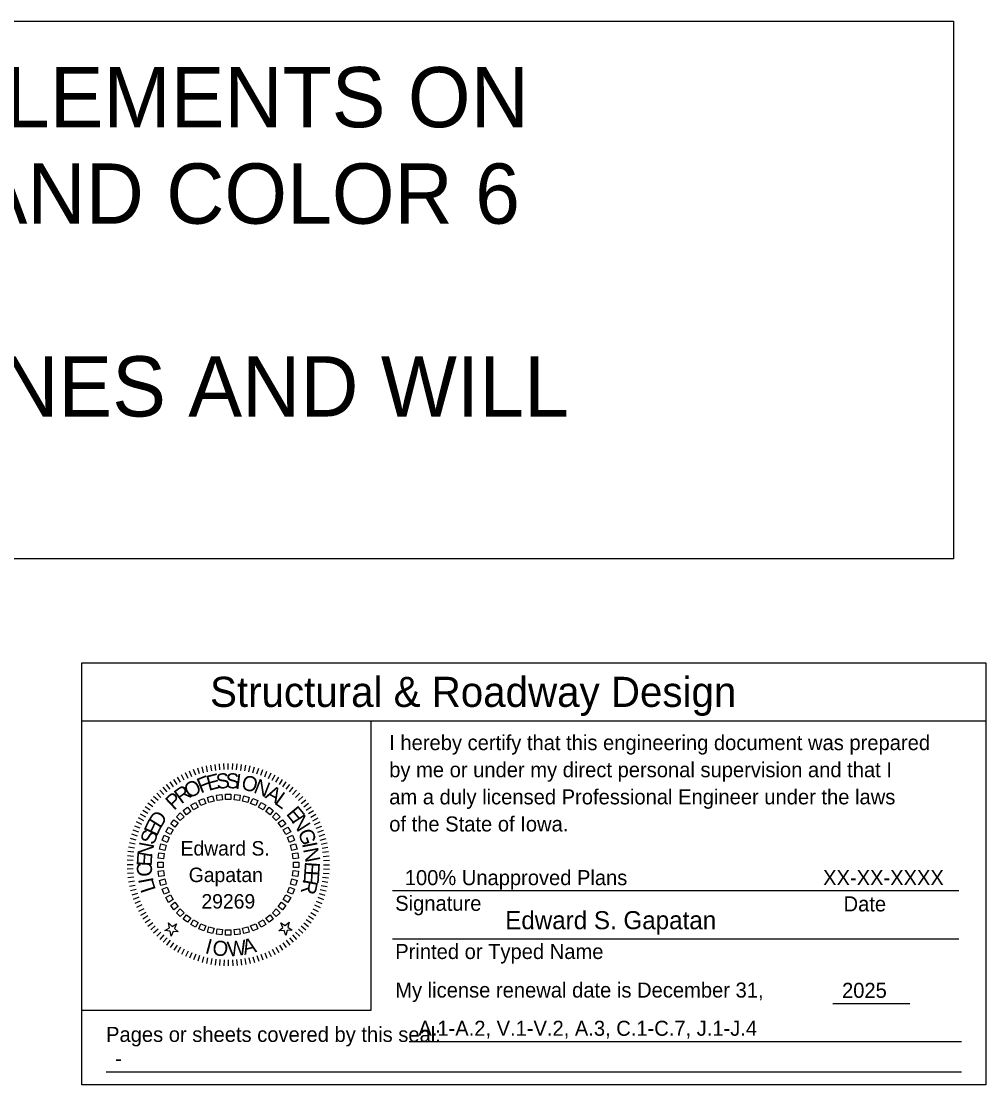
# Model space of a CAD drawing. Extents: x -0.84 to 4.97, y -1.01 to 2.42.
# Drawn here: x 3.618 to 4.285, y -0.653 to 0.082 of the extents above; entities that cross this region are included whole.
import ezdxf

# ---------------------------------------------------------------- set-up
doc = ezdxf.new("R2010")
doc.units = 0
for name, color, linetype in [('Level 1', 7, 'Continuous'), ('Level 2', 7, 'Continuous'), ('SheetGridMajor', 7, 'Continuous'), ('SheetGridMinor', 7, 'Continuous'), ('SheetText', 7, 'Continuous'), ('TextNonPlot', 7, 'Continuous')]:
    doc.layers.add(name, color=color, linetype=linetype)

msp = doc.modelspace()

# ---------------------------------------------------------------- linework, layer by layer
at = {"layer": 'Level 1'}
for p, q in [((3.74438, -0.43744), (3.7433, -0.43342)), ((3.74717, -0.43676), (3.74626, -0.43269)), ((3.74998, -0.4362), (3.74926, -0.4321)), ((3.75282, -0.43576), (3.75228, -0.43163)), ((3.75568, -0.43545), (3.75532, -0.4313)), ((3.75855, -0.43526), (3.75836, -0.4311)), ((3.76142, -0.4352), (3.76142, -0.43103)), ((3.76429, -0.43526), (3.76447, -0.4311)), ((3.76715, -0.43545), (3.76752, -0.4313)), ((3.77001, -0.43576), (3.77055, -0.43163)), ((3.77285, -0.4362), (3.77357, -0.4321)), ((3.77567, -0.43676), (3.77657, -0.43269)), ((3.77846, -0.43744), (3.77953, -0.43342)), ((3.7285, -0.44402), (3.72642, -0.44041)), ((3.73102, -0.44264), (3.72909, -0.43894)), ((3.73359, -0.44137), (3.73183, -0.43759)), ((3.73622, -0.44021), (3.73463, -0.43636)), ((3.7389, -0.43917), (3.73747, -0.43526)), ((3.74162, -0.43825), (3.74037, -0.43427)), ((3.78121, -0.43825), (3.78247, -0.43427)), ((3.78393, -0.43917), (3.78536, -0.43526)), ((3.78661, -0.44021), (3.7882, -0.43636)), ((3.78924, -0.44137), (3.791, -0.43759)), ((3.79181, -0.44264), (3.79374, -0.43894)), ((3.79433, -0.44402), (3.79642, -0.44041)), ((3.7191, -0.4506), (3.71642, -0.44741)), ((3.72134, -0.4488), (3.7188, -0.4455)), ((3.72365, -0.44711), (3.72127, -0.44369)), ((3.72604, -0.44551), (3.7238, -0.442)), ((3.79679, -0.44551), (3.79903, -0.442)), ((3.79918, -0.44711), (3.80157, -0.44369)), ((3.80149, -0.44881), (3.80403, -0.4455)), ((3.80373, -0.4506), (3.80641, -0.44741)), ((3.71288, -0.45656), (3.70981, -0.45374)), ((3.71486, -0.45448), (3.71192, -0.45154)), ((3.71694, -0.4525), (3.71412, -0.44942)), ((3.80589, -0.4525), (3.80871, -0.44943)), ((3.80797, -0.45448), (3.81091, -0.45154)), ((3.80995, -0.45656), (3.81303, -0.45374)), ((3.70749, -0.46327), (3.70407, -0.46088)), ((3.70919, -0.46096), (3.70588, -0.45842)), ((3.71098, -0.45872), (3.70779, -0.45604)), ((3.81185, -0.45872), (3.81504, -0.45604)), ((3.81365, -0.46096), (3.81695, -0.45842)), ((3.81534, -0.46327), (3.81876, -0.46088)), ((3.70302, -0.47064), (3.69932, -0.46871)), ((3.7044, -0.46812), (3.70079, -0.46603)), ((3.70589, -0.46566), (3.70238, -0.46342)), ((3.81694, -0.46566), (3.82045, -0.46342)), ((3.81843, -0.46812), (3.82204, -0.46603)), ((3.81981, -0.47064), (3.82351, -0.46871)), ((3.69955, -0.47852), (3.69564, -0.47709)), ((3.70059, -0.47584), (3.69674, -0.47425)), ((3.70175, -0.47321), (3.69797, -0.47145)), ((3.82108, -0.47321), (3.82486, -0.47145)), ((3.82224, -0.47584), (3.82609, -0.47425)), ((3.82328, -0.47852), (3.82719, -0.47709)), ((3.69783, -0.48399), (3.6938, -0.48292)), ((3.69863, -0.48124), (3.69466, -0.47998)), ((3.8242, -0.48124), (3.82818, -0.47999)), ((3.82501, -0.484), (3.82903, -0.48292)), ((3.69615, -0.49244), (3.69201, -0.4919)), ((3.69658, -0.4896), (3.69248, -0.48888)), ((3.69714, -0.48678), (3.69307, -0.48588)), ((3.82569, -0.48679), (3.82976, -0.48588)), ((3.82625, -0.4896), (3.83035, -0.48888)), ((3.82669, -0.49244), (3.83082, -0.4919)), ((3.69564, -0.49816), (3.69148, -0.49798)), ((3.69583, -0.4953), (3.69168, -0.49493)), ((3.827, -0.4953), (3.83115, -0.49493)), ((3.82719, -0.49816), (3.83135, -0.49798)), ((3.69558, -0.50103), (3.69141, -0.50103)), ((3.69564, -0.5039), (3.69148, -0.50409)), ((3.69583, -0.50677), (3.69168, -0.50713)), ((3.827, -0.50677), (3.83115, -0.50714)), ((3.82719, -0.50391), (3.83135, -0.50409)), ((3.82725, -0.50103), (3.83142, -0.50103)), ((3.69614, -0.50963), (3.69201, -0.51017)), ((3.69658, -0.51247), (3.69248, -0.51319)), ((3.82625, -0.51247), (3.83035, -0.51319)), ((3.82669, -0.50963), (3.83082, -0.51017)), ((3.69714, -0.51528), (3.69307, -0.51618)), ((3.69783, -0.51807), (3.6938, -0.51915)), ((3.69863, -0.52083), (3.69465, -0.52208)), ((3.8242, -0.52083), (3.82818, -0.52208)), ((3.82501, -0.51807), (3.82903, -0.51915)), ((3.82569, -0.51528), (3.82976, -0.51618)), ((3.69955, -0.52355), (3.69564, -0.52497)), ((3.70059, -0.52623), (3.69674, -0.52782)), ((3.70175, -0.52886), (3.69797, -0.53062)), ((3.82108, -0.52886), (3.82486, -0.53062)), ((3.82224, -0.52623), (3.82609, -0.52782)), ((3.82328, -0.52355), (3.82719, -0.52498)), ((3.70302, -0.53143), (3.69932, -0.53336)), ((3.7044, -0.53395), (3.70079, -0.53603)), ((3.70589, -0.53641), (3.70238, -0.53864)), ((3.81694, -0.53641), (3.82045, -0.53864)), ((3.81843, -0.53395), (3.82204, -0.53603)), ((3.81981, -0.53143), (3.82351, -0.53336)), ((3.70749, -0.53879), (3.70407, -0.54118)), ((3.70919, -0.54111), (3.70588, -0.54365)), ((3.71098, -0.54335), (3.70779, -0.54603)), ((3.81185, -0.54335), (3.81504, -0.54603)), ((3.81364, -0.54111), (3.81695, -0.54365)), ((3.81534, -0.53879), (3.81876, -0.54118)), ((3.71288, -0.54551), (3.7098, -0.54832)), ((3.71486, -0.54758), (3.71192, -0.55053)), ((3.71694, -0.54957), (3.71412, -0.55264)), ((3.7191, -0.55146), (3.71642, -0.55466)), ((3.80373, -0.55147), (3.80641, -0.55466)), ((3.80589, -0.54957), (3.80871, -0.55264)), ((3.80797, -0.54759), (3.81091, -0.55053)), ((3.80995, -0.54551), (3.81302, -0.54833)), ((3.72134, -0.55326), (3.7188, -0.55657)), ((3.72365, -0.55496), (3.72126, -0.55837)), ((3.72604, -0.55656), (3.7238, -0.56007)), ((3.7285, -0.55805), (3.72641, -0.56165)), ((3.79433, -0.55805), (3.79642, -0.56166)), ((3.79679, -0.55656), (3.79903, -0.56007)), ((3.79918, -0.55496), (3.80157, -0.55837)), ((3.80149, -0.55326), (3.80403, -0.55657)), ((3.73102, -0.55943), (3.72909, -0.56312)), ((3.73359, -0.5607), (3.73183, -0.56447)), ((3.73622, -0.56186), (3.73463, -0.5657)), ((3.7389, -0.5629), (3.73747, -0.56681)), ((3.74162, -0.56382), (3.74036, -0.56779)), ((3.74438, -0.56462), (3.7433, -0.56865)), ((3.74717, -0.56531), (3.74626, -0.56937)), ((3.74998, -0.56587), (3.74926, -0.56997)), ((3.77285, -0.56587), (3.77357, -0.56997)), ((3.77566, -0.56531), (3.77657, -0.56937)), ((3.77845, -0.56462), (3.77953, -0.56865)), ((3.78121, -0.56382), (3.78246, -0.56779)), ((3.78393, -0.5629), (3.78536, -0.56681)), ((3.78661, -0.56186), (3.7882, -0.56571)), ((3.78924, -0.5607), (3.791, -0.56448)), ((3.79181, -0.55943), (3.79374, -0.56312)), ((3.75282, -0.5663), (3.75228, -0.57043)), ((3.75568, -0.56662), (3.75531, -0.57077)), ((3.75854, -0.5668), (3.75836, -0.57097)), ((3.76142, -0.56687), (3.76142, -0.57103)), ((3.76429, -0.5668), (3.76447, -0.57097)), ((3.76715, -0.56662), (3.76752, -0.57077)), ((3.77001, -0.5663), (3.77055, -0.57043))]:
    msp.add_line(p, q, dxfattribs=at)
for points in [[(3.74593, -0.45874), (3.74246, -0.46018), (3.74103, -0.45671), (3.74449, -0.45528)], [(3.75158, -0.45708), (3.74796, -0.45805), (3.74699, -0.45443), (3.75061, -0.45346)], [(3.7574, -0.45617), (3.75368, -0.45666), (3.75319, -0.45295), (3.75691, -0.45246)], [(3.76329, -0.45603), (3.75954, -0.45603), (3.75954, -0.45228), (3.76329, -0.45228)], [(3.76915, -0.45666), (3.76543, -0.45617), (3.76592, -0.45246), (3.76964, -0.45295)], [(3.77487, -0.45805), (3.77125, -0.45708), (3.77222, -0.45346), (3.77584, -0.45443)], [(3.78037, -0.46018), (3.7769, -0.45874), (3.77834, -0.45528), (3.7818, -0.45671)], [(3.73551, -0.46419), (3.73253, -0.46647), (3.73025, -0.4635), (3.73322, -0.46122)], [(3.74054, -0.46112), (3.73729, -0.463), (3.73542, -0.45975), (3.73866, -0.45788)], [(3.78554, -0.463), (3.78229, -0.46113), (3.78417, -0.45788), (3.78741, -0.45975)], [(3.7903, -0.46647), (3.78732, -0.46419), (3.78961, -0.46122), (3.79258, -0.4635)], [(3.72685, -0.47215), (3.72457, -0.47513), (3.7216, -0.47284), (3.72388, -0.46987)], [(3.73092, -0.46789), (3.72827, -0.47054), (3.72562, -0.46789), (3.72827, -0.46524)], [(3.79456, -0.47054), (3.79191, -0.46789), (3.79456, -0.46524), (3.79721, -0.46789)], [(3.79826, -0.47513), (3.79598, -0.47215), (3.79895, -0.46987), (3.80123, -0.47284)], [(3.72338, -0.47691), (3.72151, -0.48016), (3.71826, -0.47828), (3.72013, -0.47504)], [(3.80133, -0.48016), (3.79945, -0.47691), (3.8027, -0.47503), (3.80457, -0.47828)], [(3.72056, -0.48208), (3.71912, -0.48555), (3.71566, -0.48411), (3.71709, -0.48065)], [(3.80371, -0.48555), (3.80227, -0.48208), (3.80574, -0.48065), (3.80717, -0.48411)], [(3.71843, -0.48758), (3.71746, -0.4912), (3.71384, -0.49023), (3.71481, -0.48661)], [(3.80537, -0.4912), (3.8044, -0.48758), (3.80802, -0.4866), (3.80899, -0.49023)], [(3.71641, -0.49916), (3.71641, -0.50291), (3.71266, -0.50291), (3.71266, -0.49916)], [(3.71704, -0.4933), (3.71656, -0.49702), (3.71284, -0.49653), (3.71333, -0.49281)], [(3.80628, -0.49702), (3.80579, -0.4933), (3.8095, -0.49281), (3.80999, -0.49653)], [(3.80642, -0.50291), (3.80642, -0.49916), (3.81017, -0.49916), (3.81017, -0.50291)], [(3.71655, -0.50505), (3.71704, -0.50877), (3.71333, -0.50926), (3.71284, -0.50554)], [(3.80579, -0.50877), (3.80628, -0.50505), (3.80999, -0.50554), (3.8095, -0.50926)], [(3.71746, -0.51087), (3.71843, -0.51449), (3.71481, -0.51546), (3.71384, -0.51184)], [(3.8044, -0.51449), (3.80537, -0.51087), (3.80899, -0.51184), (3.80802, -0.51546)], [(3.71912, -0.51652), (3.72056, -0.51999), (3.71709, -0.52142), (3.71566, -0.51796)], [(3.72151, -0.52191), (3.72338, -0.52516), (3.72013, -0.52703), (3.71826, -0.52379)], [(3.79945, -0.52516), (3.80132, -0.52191), (3.80457, -0.52379), (3.8027, -0.52703)], [(3.80227, -0.51999), (3.80371, -0.51652), (3.80717, -0.51796), (3.80574, -0.52142)], [(3.72457, -0.52694), (3.72686, -0.52992), (3.72388, -0.5322), (3.7216, -0.52922)], [(3.79598, -0.52992), (3.79826, -0.52694), (3.80123, -0.52922), (3.79895, -0.5322)], [(3.72827, -0.53153), (3.73092, -0.53418), (3.72827, -0.53683), (3.72562, -0.53418)], [(3.73253, -0.53559), (3.73551, -0.53788), (3.73322, -0.54085), (3.73025, -0.53857)], [(3.78732, -0.53788), (3.7903, -0.53559), (3.79258, -0.53857), (3.78961, -0.54085)], [(3.79191, -0.53418), (3.79456, -0.53153), (3.79721, -0.53418), (3.79456, -0.53683)], [(3.71998, -0.54126), (3.72261, -0.54363), (3.72569, -0.54186), (3.72424, -0.5451), (3.72688, -0.54747), (3.72335, -0.5471), (3.72191, -0.55034), (3.72117, -0.54687), (3.71765, -0.5465), (3.72072, -0.54473)], [(3.73729, -0.53907), (3.74054, -0.54094), (3.73866, -0.54419), (3.73542, -0.54232)], [(3.74246, -0.54189), (3.74593, -0.54333), (3.74449, -0.54679), (3.74103, -0.54536)], [(3.74796, -0.54402), (3.75158, -0.54499), (3.75061, -0.54861), (3.74699, -0.54764)], [(3.77125, -0.54499), (3.77487, -0.54401), (3.77585, -0.54764), (3.77222, -0.54861)], [(3.7769, -0.54333), (3.78037, -0.54189), (3.7818, -0.54536), (3.77834, -0.54679)], [(3.78229, -0.54094), (3.78554, -0.53907), (3.78742, -0.54232), (3.78417, -0.54419)], [(3.79783, -0.54124), (3.80084, -0.54312), (3.80356, -0.54085), (3.8027, -0.54429), (3.8057, -0.54616), (3.80217, -0.54641), (3.80131, -0.54985), (3.79998, -0.54656), (3.79644, -0.54681), (3.79916, -0.54453)], [(3.75368, -0.5454), (3.7574, -0.54589), (3.75691, -0.54961), (3.75319, -0.54912)], [(3.75954, -0.54603), (3.76329, -0.54603), (3.76329, -0.54978), (3.75954, -0.54978)], [(3.76543, -0.54589), (3.76915, -0.5454), (3.76964, -0.54912), (3.76592, -0.54961)]]:
    msp.add_lwpolyline(points, close=True, dxfattribs=at)
at = {"layer": 'SheetGridMajor'}
for p, q in [((3.66019, -0.40149), (4.28519, -0.40149)), ((3.86019, -0.60149), (3.86019, -0.40149)), ((3.66019, -0.60149), (3.86019, -0.60149))]:
    msp.add_line(p, q, dxfattribs=at)
msp.add_lwpolyline([(3.66019, -0.36149), (4.28519, -0.36149), (4.28519, -0.65315), (3.66019, -0.65315)], close=True, dxfattribs=at)
at = {"layer": 'SheetGridMinor'}
for p, q in [((4.26654, -0.51918), (3.87487, -0.51918)), ((4.26654, -0.55251), (3.87487, -0.55251)), ((4.23265, -0.59711), (4.17948, -0.59711)), ((3.88651, -0.62335), (4.26853, -0.62335)), ((3.88651, -0.62335), (4.26853, -0.62335)), ((3.67691, -0.64418), (4.26853, -0.64418))]:
    msp.add_line(p, q, dxfattribs=at)
at = {"layer": 'TextNonPlot'}
msp.add_lwpolyline([(4.263, -0.28939), (2.87556, -0.28939), (2.87556, 0.08223), (4.263, 0.08223)], close=True, dxfattribs=at)

# ---------------------------------------------------------------- texts
at = {"layer": 'Level 1'}
for s, rotation, p in [('F', 21.77363, (3.74236, -0.45178)), ('E', 14.58234, (3.74782, -0.45)), ('S', 7.39106, (3.75367, -0.44878)), ('S', 0.19978, (3.75976, -0.44823)), ('I', 353.00849, (3.76587, -0.44837)), ('O', 345.81721, (3.76981, -0.44868)), ('R', 36.1562, (3.72889, -0.45939)), ('O', 28.96491, (3.73443, -0.45561)), ('N', 338.62592, (3.77834, -0.45094)), ('A', 331.43464, (3.78636, -0.45448)), ('P', 43.34748, (3.72393, -0.46379)), ('L', 324.24335, (3.79269, -0.45848)), ('E', 309.86078, (3.80101, -0.46605)), ('E', 64.92134, (3.71203, -0.48195)), ('D', 57.73005, (3.71446, -0.47647)), ('N', 302.6695, (3.80473, -0.47074)), ('S', 72.11262, (3.71019, -0.48779)), ('G', 288.28693, (3.80948, -0.47818)), ('N', 79.30391, (3.70854, -0.49642)), ('I', 281.09564, (3.81236, -0.48639)), ('N', 281.09564, (3.81312, -0.49025)), ('C', 93.68648, (3.70901, -0.50899)), ('E', 86.49519, (3.70842, -0.50242)), ('E', 266.27731, (3.81449, -0.49873)), ('E', 266.27731, (3.8141, -0.5047)), ('I', 100.87776, (3.70991, -0.51284)), ('L', 108.06904, (3.71148, -0.51825)), ('R', 259.08602, (3.81335, -0.51063)), ('I', 345.29061, (3.74485, -0.56206)), ('O', 352.48189, (3.74995, -0.5633)), ('W', 6.86446, (3.76136, -0.56473)), ('A', 14.05574, (3.77253, -0.56343))]:
    msp.add_text(s, height=0.01042, rotation=rotation, dxfattribs=at).set_placement(p)
at = {"layer": 'Level 2'}
for s, p in [('Edward S.', (3.72842, -0.4947)), ('Gapatan', (3.73407, -0.51303)), ('29269', (3.74286, -0.53136))]:
    msp.add_text(s, height=0.01, dxfattribs=at).set_placement(p)
at = {"layer": 'SheetText'}
for s, height, p in [('Structural & Roadway Design', 0.0208333, (3.74883, -0.3919)), ('I hereby certify that this engineering document was prepared', 0.0104167, (3.87271, -0.42179)), ('by me or under my direct personal supervision and that I', 0.0104167, (3.87271, -0.44054)), ('am a duly licensed Professional Engineer under the laws', 0.0104167, (3.87271, -0.45929)), ('of the State of Iowa.', 0.0104167, (3.87271, -0.47804)), ('100% Unapproved Plans', 0.0104, (3.88349, -0.51515)), ('XX-XX-XXXX', 0.0104, (4.17275, -0.51515)), ('Signature', 0.010417, (3.87686, -0.53289)), ('Date', 0.010417, (4.1869, -0.53331)), ('Edward S. Gapatan', 0.0125, (3.95293, -0.54562)), ('Printed or Typed Name', 0.0104167, (3.87686, -0.56623)), ('My license renewal date is December 31,', 0.0104167, (3.87686, -0.59289)), ('2025', 0.0104, (4.18585, -0.59309)), ('A.1-A.2, V.1-V.2, A.3, C.1-C.7, J.1-J.4', 0.0104, (3.89288, -0.61932)), ('Pages or sheets covered by this seal:', 0.0104167, (3.67691, -0.62355)), ('-', 0.0104, (3.68328, -0.64015))]:
    msp.add_text(s, height=height, dxfattribs=at).set_placement(p)
at = {"layer": 'TextNonPlot'}
for s, p in [('ALL TEXT AND LINEAR ELEMENTS ON ', (2.94745, 0.00892)), ('THE TextNonPlot LEVEL AND COLOR 6 ', (2.94745, -0.05775)), ('INSTRUCTIONS/GUIDELINES AND WILL ', (2.94745, -0.19108))]:
    msp.add_text(s, height=0.0416667, dxfattribs=at).set_placement(p)

doc.saveas('drawing.dxf')
